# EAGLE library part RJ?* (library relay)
SMD RELAYS WITH 5GHz CAPABILITIES NAiS Source: http://www.mew-europe.com/.. en_ds_61313_0000.pdf
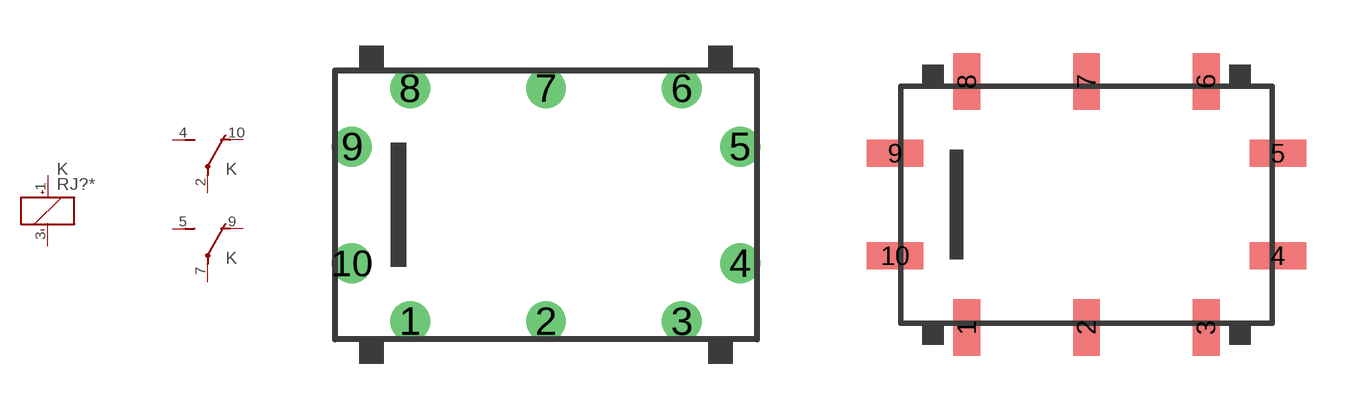
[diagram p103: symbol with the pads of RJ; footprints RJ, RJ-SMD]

Designator prefix K; gates 1=K+- 2=U 3=U

## RJ2003 (MPN: ARJ2003; OC_FARNELL: unknown; OC_NEWARK: 11N2927), RJ204H (MF: AROMAT/ MATSUSHITA; MPN: ARJ204H; OC_FARNELL: unknown; OC_NEWARK: 63H2424), RJ2012 (MF: AROMAT/ MATSUSHITA; MPN: ARJ2012; OC_FARNELL: unknown; OC_NEWARK: 81C8602), RJ2024 (MPN: ARJ2024; OC_FARNELL: unknown; OC_NEWARK: 11N2928)  [RJ]
1  1:+  pas
2  2:P  pas
3  1:-  pas
4  2:S  pas
5  3:S  pas
7  3:P  pas
9  3:O  pas
10  2:O  pas

## RJ20A03 (MPN: ARJ20A03; OC_FARNELL: unknown; OC_NEWARK: 11N2921), RJ20A4H (MPN: ARJ20A4H; OC_FARNELL: unknown; OC_NEWARK: 13P1248), RJ20A12 (MPN: ARJ20A12; OC_FARNELL: 8928207; OC_NEWARK: 13P1247), RJ20A24 (MPN: ARJ20A24; OC_FARNELL: unknown; OC_NEWARK: 11N2924)  [RJ-SMD]
Pads as for RJ

## Footprint RJ (pad centres in mm)
SMD RELAYS WITH 5GHz CAPABILITIES NAiS Source: http://www.mew-europe.com/.. en_ds_61313_0000.pdf
drill 0.8 round: 1 -4.445,-3.81; 2 0,-3.81; 3 4.445,-3.81; 4 6.35,-1.905; 5 6.35,1.905; 6 4.445,3.81; 7 0,3.81; 8 -4.445,3.81; 9 -6.35,1.905; 10 -6.35,-1.905

## Footprint RJ-SMD (pad centres in mm)
SMD RELAYS WITH 5GHz CAPABILITIES NAiS Source: http://www.mew-europe.com/.. en_ds_61313_0000.pdf
smd 1 x 2.1: 1 -4.445,-4.572; 2 0,-4.572; 3 4.445,-4.572; 6 4.445,4.572; 7 0,4.572; 8 -4.445,4.572
smd 2.1 x 1: 4 7.112,-1.905; 5 7.112,1.905; 9 -7.112,1.905; 10 -7.112,-1.905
